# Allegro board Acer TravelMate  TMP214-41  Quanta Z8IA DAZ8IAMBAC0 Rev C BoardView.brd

Outline 238 x 219.5 mm; copper layers: TOP, SGND, IN1, SVCC, IN2, IN3, SGND1, IN4, SGND2, BOTTOM. Coordinates in mm from the lower left corner of the outline.

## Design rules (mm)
constraint set DEFAULT: min track width 0.114
net group W3.5-T1234B: nets VGA_VCCSENSE VGA_VSSSENSE
net group W4-T1234B: nets +1.2VSUS +VCC3V3A_SX_TCP0
net group W12-T1234B: nets +3VLCD_CON_R_C +VCONN_5V_3
net group W15-T134B: nets CLK_BIASREF DDR_RCOMP0
net group DFP-S4(3.5: nets PEX_TSTCLK PEX_TSTCLK# VMA_CLK0 VMA_CLK0# VMA_CLK1 VMA_CLK1# VMA_WCK01 VMA_WCK01# VMA_WCK23 VMA_WCK23# VMA_WCK45 VMA_WCK45# VMA_WCK67 VMA_WCK67#
net group DFP-S4.5(3.5: nets M_A_CLKN0 M_A_CLKN1 M_A_CLKP0 M_A_CLKP1 M_B_CLKN0 M_B_CLKN1 M_B_CLKP0 M_B_CLKP1
net group DFP-S4.5(3.5: nets CLK_PCIE_LANN CLK_PCIE_LANP CLK_PCIE_SSDN CLK_PCIE_SSDN_C CLK_PCIE_SSDP CLK_PCIE_SSDP_C CLK_PCIE_WLANN CLK_PCIE_WLANP CLK_VGA_N CLK_VGA_P CNV_WR_CLK_DN CNV_WR_CLK_DP CNV_WR_LANE0_DN CNV_WR_LANE0_DP CNV_WR_LANE1_DN CNV_WR_LANE1_DP CNV_WT_CLK_DN CNV_WT_CLK_DP CNV_WT_LANE0_DN CNV_WT_LANE0_DP CNV_WT_LANE1_DN CNV_WT_LANE1_DP DP_AUXN DP_AUXP DP_D0N DP_D0P DP_D1N DP_D1P GPU_CLK#_C GPU_CLK_C GPU_D0#_C GPU_D0_C GPU_D1#_C GPU_D1_C GPU_D2#_C GPU_D2_C HDMI_TXCN HDMI_TXCP HDMI_TXDN0 HDMI_TXDN1 HDMI_TXDN2 HDMI_TXDP0 HDMI_TXDP1 HDMI_TXDP2 INT_EDP_AUXN INT_EDP_AUXN_C INT_EDP_AUXP INT_EDP_AUXP_C INT_EDP_TXN0 INT_EDP_TXN0_C INT_EDP_TXN1 INT_EDP_TXN1_C INT_EDP_TXP0 INT_EDP_TXP0_C INT_EDP_TXP1 INT_EDP_TXP1_C PCIE4_RCOMPN PCIE4_RCOMPP PCIE_RCOMPN PCIE_RCOMPP PCIE_RXN3_WLAN PCIE_RXN5_SSD PCIE_RXN5_SSD_C PCIE_RXN6_SSD PCIE_RXN6_SSD_C PCIE_RXN7_SSD PCIE_RXN7_SSD_C PCIE_RXN8_SSD PCIE_RXN8_SSD_C PCIE_RXN9_LAN PCIE_RXN_LAN_L PCIE_RXP3_WLAN PCIE_RXP5_SSD PCIE_RXP5_SSD_C PCIE_RXP6_SSD PCIE_RXP6_SSD_C PCIE_RXP7_SSD PCIE_RXP7_SSD_C PCIE_RXP8_SSD PCIE_RXP8_SSD_C PCIE_RXP9_LAN PCIE_RXP_LAN_L PCIE_TXN3_WLAN PCIE_TXN3_WLAN_C PCIE_TXN5_SSD PCIE_TXN5_SSD_C PCIE_TXN6_SSD PCIE_TXN6_SSD_C PCIE_TXN7_SSD PCIE_TXN7_SSD_C PCIE_TXN8_SSD PCIE_TXN8_SSD_C PCIE_TXN9_LAN PCIE_TXN9_LAN_C PCIE_TXP3_WLAN PCIE_TXP3_WLAN_C PCIE_TXP5_SSD PCIE_TXP5_SSD_C PCIE_TXP6_SSD PCIE_TXP6_SSD_C PCIE_TXP7_SSD PCIE_TXP7_SSD_C PCIE_TXP8_SSD PCIE_TXP8_SSD_C PCIE_TXP9_LAN PCIE_TXP9_LAN_C PEG_RXN1 PEG_RXN1_C PEG_RXN2 PEG_RXN2_C PEG_RXN3 PEG_RXN3_C PEG_RXN4 PEG_RXN4_C PEG_RXP1 PEG_RXP1_C PEG_RXP2 PEG_RXP2_C PEG_RXP3 PEG_RXP3_C PEG_RXP4 PEG_RXP4_C PEG_TXN1 PEG_TXN1_C PEG_TXN2 PEG_TXN2_C PEG_TXN3 PEG_TXN3_C PEG_TXN4 PEG_TXN4_C PEG_TXP1 PEG_TXP1_C PEG_TXP2 PEG_TXP2_C PEG_TXP3 PEG_TXP3_C PEG_TXP4 PEG_TXP4_C SATA_RXN0_CN SATA_RXN0_HDD SATA_RXN0_IN SATA_RXN_OUT SATA_RXP0_CN SATA_RXP0_HDD SATA_RXP0_IN SATA_RXP_OUT SATA_TXN0_CN SATA_TXN0_HDD SATA_TXN0_IN SATA_TXN_OUT SATA_TXP0_CN SATA_TXP0_HDD SATA_TXP0_IN SATA_TXP_OUT TBT_LSX0_RXD TBT_LSX0_RXD_SOC TBT_LSX0_TXD TBT_LSX0_TXD_SOC TBTA_SBU1_CCG5_L TBTA_SBU1_CCG5_R TBTA_SBU1_CON_CCG5 TBTA_SBU2_CCG5_L TBTA_SBU2_CCG5_R TBTA_SBU2_CON_CCG5 TCP0_AUX_DN TCP0_AUX_DN_R TCP0_AUX_DP TCP0_AUX_DP_R TCP0_TX_N0 TCP0_TX_N0_C TCP0_TX_N1 TCP0_TX_N1_C TCP0_TX_P0 TCP0_TX_P0_C TCP0_TX_P1 TCP0_TX_P1_C TCP0_TXRX_N0 TCP0_TXRX_N0_C TCP0_TXRX_N1 TCP0_TXRX_N1_C TCP0_TXRX_P0 TCP0_TXRX_P0_C TCP0_TXRX_P1 TCP0_TXRX_P1_C TCRCOMP_DN TCRCOMP_DP USB30_RX1+ USB30_RX1+_C USB30_RX1- USB30_RX1-_C USB30_RX2+ USB30_RX2+_C USB30_RX2- USB30_RX2-_C USB30_RX4+ USB30_RX4- USB30_TX1+ USB30_TX1+_C USB30_TX1+_C_R USB30_TX1- USB30_TX1-_C USB30_TX1-_C_R USB30_TX2+ USB30_TX2+_C USB30_TX2+_C_R USB30_TX2- USB30_TX2-_C USB30_TX2-_C_R USB30_TX4+ USB30_TX4- USBP1+_CR USBP1-_CR USBP2+_TPC USBP2+_TPC_BOT USBP2+_TPC_TOP USBP2-_TPC USBP2-_TPC_BOT USBP2-_TPC_TOP USBP3+_LTE USBP3-_LTE USBP4+ USBP4+_R USBP4- USBP4-_R USBP5+_CAM USBP5+_CAM_C USBP5-_CAM USBP5-_CAM_C USBP6+_HUB USBP6+_HUB_R USBP6+_HUB_SM USBP6+_HUB_SM_R USBP6+_HUB_TS USBP6+_HUB_TS_R USBP6-_HUB USBP6-_HUB_R USBP6-_HUB_SM USBP6-_HUB_SM_R USBP6-_HUB_TS USBP6-_HUB_TS_R USBP7+_FP_P2 USBP7+_FP_P4 USBP7-_FP_P2 USBP7-_FP_P4 USBP8+ USBP8+_C USBP8+_C_R USBP8- USBP8-_C USBP8-_C_R USBP9+_DB USBP9+_DB_RS232 USBP9+_DB_USB USBP9-_DB USBP9-_DB_RS232 USBP9-_DB_USB USBP10+_BT USBP10-_BT VGA_DDI2_AUXN_C VGA_DDI2_AUXP_C VGA_DDI2_TXN0_C VGA_DDI2_TXN1_C VGA_DDI2_TXP0_C VGA_DDI2_TXP1_C
net group DFP-S4.5W4.5-TB: nets TBTA_RX1_N TBTA_RX1_P TBTA_RX2_N TBTA_RX2_P TBTA_SSRX1_N TBTA_SSRX1_N_C TBTA_SSRX1_P TBTA_SSRX1_P_C TBTA_SSRX2_N TBTA_SSRX2_N_C TBTA_SSRX2_P TBTA_SSRX2_P_C TBTA_SSTX1_N TBTA_SSTX1_N_C TBTA_SSTX1_P TBTA_SSTX1_P_C TBTA_SSTX2_N TBTA_SSTX2_N_C TBTA_SSTX2_P TBTA_SSTX2_P_C TBTA_TX1_N TBTA_TX1_P TBTA_TX2_N TBTA_TX2_P
net group DFP-S5(4.5: nets M_A_DQSN0 M_A_DQSN1 M_A_DQSN2 M_A_DQSN3 M_A_DQSN4 M_A_DQSN5 M_A_DQSN6 M_A_DQSN7 M_A_DQSP0 M_A_DQSP1 M_A_DQSP2 M_A_DQSP3 M_A_DQSP4 M_A_DQSP5 M_A_DQSP6 M_A_DQSP7 M_B_DQSN0 M_B_DQSN1 M_B_DQSN2 M_B_DQSN3 M_B_DQSN4 M_B_DQSN5 M_B_DQSN6 M_B_DQSN7 M_B_DQSP0 M_B_DQSP1 M_B_DQSP2 M_B_DQSP3 M_B_DQSP4 M_B_DQSP5 M_B_DQSP6 M_B_DQSP7
net group DFP-S5.5(7)W3.5(3.2: nets MDI0+ MDI0+_1 MDI0- MDI0-_1 MDI1+ MDI1+_1 MDI1- MDI1-_1 MDI2+ MDI2+_1 MDI2- MDI2-_1 MDI3+ MDI3+_1 MDI3- MDI3-_1
net group DFP-S5.5(7: nets C_IN_CLK C_IN_CLK# C_TX0_HDMI+ C_TX0_HDMI- C_TX1_HDMI+ C_TX1_HDMI- C_TX2_HDMI+ C_TX2_HDMI- TX0_HDMI+ TX0_HDMI- TX1_HDMI+ TX1_HDMI- TX2_HDMI+ TX2_HDMI- TXC_HDMI+ TXC_HDMI-
net group GND: nets GND
net group W4.5(3.5: nets DDR4_DRAMRST# DRAM_RESET# M_A_DQ0 M_A_DQ1 M_A_DQ2 M_A_DQ3 M_A_DQ4 M_A_DQ5 M_A_DQ6 M_A_DQ7 M_A_DQ8 M_A_DQ9 M_A_DQ10 M_A_DQ11 M_A_DQ12 M_A_DQ13 M_A_DQ14 M_A_DQ15 M_A_DQ16 M_A_DQ17 M_A_DQ18 M_A_DQ19 M_A_DQ20 M_A_DQ21 M_A_DQ22 M_A_DQ23 M_A_DQ24 M_A_DQ25 M_A_DQ26 M_A_DQ27 M_A_DQ28 M_A_DQ29 M_A_DQ30 M_A_DQ31 M_A_DQ32 M_A_DQ33 M_A_DQ34 M_A_DQ35 M_A_DQ36 M_A_DQ37 M_A_DQ38 M_A_DQ39 M_A_DQ40 M_A_DQ41 M_A_DQ42 M_A_DQ43 M_A_DQ44 M_A_DQ45 M_A_DQ46 M_A_DQ47 M_A_DQ48 M_A_DQ49 M_A_DQ50 M_A_DQ51 M_A_DQ52 M_A_DQ53 M_A_DQ54 M_A_DQ55 M_A_DQ56 M_A_DQ57 M_A_DQ58 M_A_DQ59 M_A_DQ60 M_A_DQ61 M_A_DQ62 M_A_DQ63 M_B_DQ0 M_B_DQ1 M_B_DQ2 M_B_DQ3 M_B_DQ4 M_B_DQ5 M_B_DQ6 M_B_DQ7 M_B_DQ8 M_B_DQ9 M_B_DQ10 M_B_DQ11 M_B_DQ12 M_B_DQ13 M_B_DQ14 M_B_DQ15 M_B_DQ16 M_B_DQ17 M_B_DQ18 M_B_DQ19 M_B_DQ20 M_B_DQ21 M_B_DQ22 M_B_DQ23 M_B_DQ24 M_B_DQ25 M_B_DQ26 M_B_DQ27 M_B_DQ28 M_B_DQ29 M_B_DQ30 M_B_DQ31 M_B_DQ32 M_B_DQ33 M_B_DQ34 M_B_DQ35 M_B_DQ36 M_B_DQ37 M_B_DQ38 M_B_DQ39 M_B_DQ40 M_B_DQ41 M_B_DQ42 M_B_DQ43 M_B_DQ44 M_B_DQ45 M_B_DQ46 M_B_DQ47 M_B_DQ48 M_B_DQ49 M_B_DQ50 M_B_DQ51 M_B_DQ52 M_B_DQ53 M_B_DQ54 M_B_DQ55 M_B_DQ56 M_B_DQ57 M_B_DQ58 M_B_DQ59 M_B_DQ60 M_B_DQ61 M_B_DQ62 M_B_DQ63
net group W4.5(3.5: nets ACZ_BCLK ACZ_RST# ACZ_SDOUT ACZ_SYNC BIOS_WP# CPU_SVID_CLK CPU_SVID_DAT CPU_VIDALERT# DMIC_CLK DMIC_CLK_L DMIC_CLK_L_C DMIC_CLK_PCH DMIC_DAT DMIC_DAT_L DMIC_DAT_L_C DMIC_DAT_PCH ESPI_0 ESPI_0_R ESPI_1 ESPI_1_R ESPI_2 ESPI_2_R ESPI_3 ESPI_3_R ESPI_CLK ESPI_CLK_R ESPI_CS# ESPI_CS#_R ESPI_RESET# ESPI_RESET#_EC ESPI_RESET#_R H_PROCHOT# HOLD# N17011437 PCH_AZ_CODEC_BITCLK PCH_AZ_CODEC_RST# PCH_AZ_CODEC_SDIN0 PCH_AZ_CODEC_SDOUT PCH_AZ_CODEC_SYNC PCH_JTAGX PCH_SPI0_CLK PCH_SPI0_CLK_R PCH_SPI0_CS0# PCH_SPI0_CS0#_R PCH_SPI0_IO2 PCH_SPI0_IO2_R PCH_SPI0_IO3 PCH_SPI0_IO3_R PCH_SPI0_SI PCH_SPI0_SI_R PCH_SPI0_SO PCH_SPI0_SO_R PCH_SPI1_CLK_R PCH_SPI1_SI_R PCH_SPI1_SO_R PCH_SPI_CS0#_R PCH_TCK PCH_TDI PCH_TDO PCH_TMS PCH_TRST# PEGX_RST# PEGX_RST#_C PLTRST# PLTRST#_LAN PM_THRMTRIP# PROCHOT#_CPU PROCHOT_EC PROCPWRGD SD_CDZ SD_CDZ_R SD_CLK SD_CLK_R SD_CMD SD_CMD_R SD_D0/MS_D6 SD_D0/MS_D6_R SD_D1/MS_D7 SD_D1/MS_D7_R SD_D2/MS_D5 SD_D2/MS_D5_R SD_D3/MS_D4 SD_D3/MS_D4_R SD_WP/MS_D1 SPI0_CLK_R SPI0_CS0#_R SPI0_SI_R SPI0_SO_R SPI_TPM_CS# SPI_TPM_CS#_TPM TBTA_SBU1_TX_BB TBTA_SBU2_RX_BB TCP0_FLASH_CLK TCP0_FLASH_CS# TCP0_FLASH_DI TCP0_FLASH_DO TCP0_FLASH_HOLD# TCP0_FLASH_WP# TPM_SPI0_CLK TPM_SPI0_SI TPM_SPI0_SO USB_OC2# VGA_DDC_CLK_RT VGA_DDC_DAT_RT VR_SVID_ALERT# VR_SVID_CLK VR_SVID_DATA XDP_TCK XDP_TDI_CPU XDP_TDO_CPU XDP_TMS_CPU XDP_TRST#
net group W4.5(3.5: nets 2ND_MBCLK 2ND_MBDATA 27M_XTAL_IN 27M_XTAL_OUT A_SCL A_SDA BRIGHT CL_CLK CL_DATA CL_RST# CNV_BRI_DT CNV_BRI_DT_R CNV_BRI_RSP CNV_BRI_RSP_L CNV_MFUART2_RXD CNV_MFUART2_TXD CNV_RF_RESET# CNV_RF_RESET#_L CNV_RGI_DT CNV_RGI_DT_R CNV_RGI_RSP CNV_RGI_RSP_L DDPC_CLK DDPC_DATA DISP_ON DP_HPD EC_CCG_I2C_SCL EC_CCG_I2C_SCL_D EC_CCG_I2C_SDA EC_CCG_I2C_SDA_D EC_PECI EC_PECR_R GPUT_CLK_L GPUT_DATA_L HDMI_DDCCLK HDMI_DDCCLK_DDP3 HDMI_DDCDATA HDMI_HPD HDMI_HPD_C HDMI_HPD_DC HDMI_HPD_PCH HDMI_SCLK HDMI_SDATA I2C1_CLK_TP I2C1_DATA_TP I2C2_SCL_SEN_HUB I2C2_SDA_SEN_HUB I2C3_SCL_NFC I2C3_SDA_NFC I219_PCH_SMCLK I219_PCH_SMDATA I219_SMCLK I219_SMDATA ISH_I2C1_SCL ISH_I2C1_SDA LAN_XTAL1 MBCLK MBCLK_THM MBDATA MBDATA_THM N24720119 N24720120 N27826847 N27826858 N27826869 N36446693 N64506943 NFC_I2C_SCL NFC_I2C_SDA PCH_BLON_C PCH_DISP_ON PCH_DPST_PWM PCH_LVDS_BLON PCH_SMBCLK PCH_SMBDATA PCIE_CLKREQ_LAN# PCIE_CLKREQ_SSD# PCIE_CLKREQ_VGA# PCIE_CLKREQ_WLAN# PULSAR_38P4M_REFCLK PWM-VID RT_I2C_SCL RT_I2C_SDA RTC_RST# RTC_X1 RTC_X1_R RTC_X2 RTC_X2_R SCARDCLK SCARDDATA SCL_GSENSOR SCL_GSENSOR_MB SCL_HUB_TO_CPU SDA_GSENSOR SDA_GSENSOR_MB SDA_HUB_TO_CPU SMB_ME1_CLK SMB_ME1_CLK_D SMB_ME1_DAT SMB_ME1_DAT_D SMB_RUN_CLK SMB_RUN_DAT SMB_SML0_CLK SMB_SML0_DAT SRTC_RST# SUSCLK_32K SUSCLK_32KHZ SYS_SHDN# TBT_LSX2_RXD TP_SMB_CLK TP_SMB_DATA ULT_EDP_HPD ULT_EDP_HPD_R VCC_AUX_SENSE VCCSENSE VGA_SDA VGA_SLK VSS_AUX_SENSE VSSSENSE XIN XOUT XTAL1 XTAL2 XTAL_38P4M_IN XTAL_38P4M_IN_R XTAL_38P4M_OUT XTAL_38P4M_OUT_R XTAL_TCP0_25MHZ_IN XTAL_TCP0_25MHZ_OUT
net group W4.5-T1234B: nets +VIN
net group W4.5-TB: nets CRT_B CRT_B1 CRT_G CRT_G1 CRT_R CRT_R1 CRTHSYNC CRTHSYNC_R CRTVSYNC CRTVSYNC_R
net group W6(4: nets M_A_A0 M_A_A1 M_A_A2 M_A_A3 M_A_A4 M_A_A5 M_A_A6 M_A_A7 M_A_A8 M_A_A9 M_A_A10 M_A_A11 M_A_A12 M_A_A13 M_A_ACT# M_A_ALERT# M_A_BG#0 M_A_BG#1 M_A_BS#0 M_A_BS#1 M_A_CAS# M_A_CKE0 M_A_CKE1 M_A_CS#0 M_A_CS#1 M_A_DIM0_ODT0 M_A_DIM0_ODT1 M_A_PARITY M_A_RAS# M_A_WE# M_B_A0 M_B_A1 M_B_A2 M_B_A3 M_B_A4 M_B_A5 M_B_A6 M_B_A7 M_B_A8 M_B_A9 M_B_A10 M_B_A11 M_B_A12 M_B_A13 M_B_ACT# M_B_ALERT# M_B_BG#0 M_B_BG#1 M_B_BS#0 M_B_BS#1 M_B_CAS# M_B_CKE0 M_B_CKE1 M_B_CS#0 M_B_CS#1 M_B_DIM0_ODT0 M_B_DIM0_ODT1 M_B_PARITY M_B_RAS# M_B_WE#
net group W6-T1234B: nets +3VPCU_EC
net group W7(5: nets FBA_CMD0 FBA_CMD1 FBA_CMD2 FBA_CMD3 FBA_CMD4 FBA_CMD5 FBA_CMD6 FBA_CMD7 FBA_CMD8 FBA_CMD9 FBA_CMD10 FBA_CMD11 FBA_CMD12 FBA_CMD13 FBA_CMD14 FBA_CMD15 FBA_CMD16 FBA_CMD17 FBA_CMD18 FBA_CMD19 FBA_CMD20 FBA_CMD21 FBA_CMD22 FBA_CMD23 FBA_CMD24 FBA_CMD25 FBA_CMD26 FBA_CMD27 FBA_CMD28 FBA_CMD29 FBA_CMD30 FBA_CMD31 FBA_DBI0 FBA_DBI1 FBA_DBI2 FBA_DBI3 FBA_DBI4 FBA_DBI5 FBA_DBI6 FBA_DBI7 FBA_EDC0 FBA_EDC1 FBA_EDC2 FBA_EDC3 FBA_EDC4 FBA_EDC5 FBA_EDC6 FBA_EDC7 VMA_DQ0 VMA_DQ1 VMA_DQ2 VMA_DQ3 VMA_DQ4 VMA_DQ5 VMA_DQ6 VMA_DQ7 VMA_DQ8 VMA_DQ9 VMA_DQ10 VMA_DQ11 VMA_DQ12 VMA_DQ13 VMA_DQ14 VMA_DQ15 VMA_DQ16 VMA_DQ17 VMA_DQ18 VMA_DQ19 VMA_DQ20 VMA_DQ21 VMA_DQ22 VMA_DQ23 VMA_DQ24 VMA_DQ25 VMA_DQ26 VMA_DQ27 VMA_DQ28 VMA_DQ29 VMA_DQ30 VMA_DQ31 VMA_DQ32 VMA_DQ33 VMA_DQ34 VMA_DQ35 VMA_DQ36 VMA_DQ37 VMA_DQ38 VMA_DQ39 VMA_DQ40 VMA_DQ41 VMA_DQ42 VMA_DQ43 VMA_DQ44 VMA_DQ45 VMA_DQ46 VMA_DQ47 VMA_DQ48 VMA_DQ49 VMA_DQ50 VMA_DQ51 VMA_DQ52 VMA_DQ53 VMA_DQ54 VMA_DQ55 VMA_DQ56 VMA_DQ57 VMA_DQ58 VMA_DQ59 VMA_DQ60 VMA_DQ61 VMA_DQ62 VMA_DQ63
net group W7-T1234B: nets +1.2V_HDMI
net group W8-T134B: nets CPU_POPI_RCOMP TBT1_CC1 TBT1_CC2
net group W8-T1234B: nets +1.05V_LAN +1.8V_DEEP_SUS +1V8_AON +3V +3V3_TPM +3V_DEEP_SUS +3V_LAN +3V_LDO_EC +3V_RTC +3V_S5 +3V_WLAN_P +5V_PVDD +5VA +5VPCU +A3VPCU +AZA_VDD +SENSOR_POWER +USBPWR0 +VCC0V9_SVR_TCP0 +VCC0V9_SVR_TCP0_PHASE +VCC1.05_OUT_FET +VCCPRIM_3P3 +VCCRTC +VCCST AVDD2 DVDD_IO RSET
net group W10-T134B: nets +SMDDR_VREF_DQ1_M1 CFG_RCOMP CNV_WT_RCOMP CSI_RCOMP DP_RCOMP GPP_RCOMP PCH_OPI_RCOMP SNDW_RCOMP USB2_COMP
net group W10-T1234B: nets +1.8V_S5 +1V8_GFX_MAIN +3V_EC +3VPCU_ECPLL +VDDQ_VTT +VGPU_CORE DCPRTC NV_PLLVDD SP_PLLVDD TYPEC1_USB0
net group W13-T1234B: nets +1.35V_GFX
net group W14-T1234B: nets +2.5V_SUS
net group W15-T1234B: nets +1.03_GFX +3V_SSD +V3.3DX_RT_TCP0 +VCCSTG_S2 FB_CAL_PD_VDDQ HP-L2 HP-L3 HP-R2 HP-R3 HP_JD# LINE1-L LINE1-R LINE1-VREFO-L LINE1-VREFO-R MIC2-VREFO SENSEA
net group W20-T134B: nets +SMDDR_VREF_DIMM FBA_VREFC_1 FBA_VREFC_2 SM_VREF SMDDR_VREF_DQ1_M3
net group W20-T1234B: nets +1.05V_EXT +3V_RTC_0 +3V_RTC_1 +3V_RTC_2 +3VLCD_CON +3VLCD_CON_R +5V_HDMIC +5V_KB +601_VCC +CRT_VDDA33 +USBPWR1 +USBPWRD2 +VCCSTG +VDDQ +VIN_BLIGHT +VNN_EXT CRT_VCC_R FB_CAL_TERM_GND
net group W40-T1234B: nets L_SPK+ L_SPK+_1 L_SPK+_1_VIKI L_SPK- L_SPK-_1 L_SPK-_1_VIKI R_SPK+ R_SPK+_1 R_SPK+_1_VIKI R_SPK- R_SPK-_1 R_SPK-_1_VIKI RING2 SLEEVE
net group W60-T1234B: nets +1.05V_LAN_REGOUT

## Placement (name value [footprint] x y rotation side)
C202  0.1u/6.3V_2  [C0201]  181.78 114.58 180 bottom
C203  0.1u/6.3V_2  [C0201]  181.78 113.81 180 bottom
C212  *0.1u/6.3V_2  [C0201]  79.93 96.29 0 top
C249  *0.1u/6.3V_2  [C0201]  45.74 145.21 270 top
C250  1u/10V_2  [C0201]  52.37 135.53 270 top
C251  1u/10V_2  [C0201]  46.65 103.7 270 top
C252  1u/10V_2  [C0201]  44.5 138.96 270 top
C253  1u/10V_2  [C0201]  48.8 105.79 90 top
C254  1u/10V_2  [C0201]  46.65 130.83 0 top
C255  *1u/10V_2  [C0201]  47.54 103.7 270 top
C256  1u/10V_2  [C0201]  55.42 124.74 180 top
C257  *1u/10V_2  [C0201]  47.78 105.79 90 top
C258  *1u/10V_2  [C0201]  53.13 135.53 270 top
C259  10u/6.3V_4  [C0402]  45.77 103.78 90 top
C260  *1u/10V_2  [C0201]  55.16 110.64 0 top
C261  *10u/6.3V_4  [C0402]  56.47 107.2 270 top
C262  *1u/10V_2  [C0201]  47.29 168.81 90 top
C263  *1u/10V_2  [C0201]  44.34 144.8 90 top
C264  0.1u/6.3V_2  [C0201]  46.48 128.56 0 top
C265  2.2u/10V_4  [C0402]  46.02 127.04 180 top
C266  0.022u/25V_4  [C0402]  45.38 119.66 90 top
C267  10u/6.3V_4  [C0402]  47.46 115.51 0 top
C268  10u/6.3V_4  [C0402]  44.45 133.83 270 top
C269  1u/10V_2  [C0201]  51.61 103.07 270 top
C270  10u/6.3V_4  [C0402]  44.5 140.74 90 top
C271  *1u/10V_2  [C0201]  50.72 103.07 270 top
C272  10u/6.3V_4  [C0402]  58.58 141.84 180 top
C273  *10u/6.3V_4  [C0402]  51.27 106.69 270 top
C274  *10u/6.3V_4  [C0402]  46.64 158.99 180 top
C275  10u/6.3V_4  [C0402]  50.26 106.69 270 top
C276  *10u/6.3V_4  [C0402]  54.53 133.75 0 top
C277  *10u/6.3V_4  [C0402]  54.02 144.55 270 top
C278  0.1u/6.3V_2  [C0201]  53.69 106.4 0 top
C279  *10u/6.3V_4  [C0402]  44.5 143.02 270 top
C280  2.2u/10V_4  [C0402]  52.68 106.84 270 top
C347  EV@22u/6.3V_6  [C0603]  141.19 209.9 180 bottom
C348  EV@10u/6.3V_4  [C0402]  142.82 208.33 270 bottom
C349  EV@4.7u/6.3V_4  [C0402]  143.66 209.8 0 bottom
C350  EV@4.7u/6.3V_4  [C0402]  141.73 211.2 180 bottom
C351  EV@1u/10V_2  [C0201]  130.02 195.09 90 top
C352  EV@1u/10V_2  [C0201]  134.16 195.73 270 top
C353  EV@1u/10V_2  [C0201]  135.43 191.54 270 top
C354  EV@1u/10V_2  [C0201]  143.05 209.19 270 top
C355  EV@47u/6.3V_6  [C0603]  138.45 210.86 270 bottom
C356  EV@4.7u/6.3V_4  [C0402]  140.81 208.21 0 bottom
C357  EV@4.7u/6.3V_4  [C0402]  134.15 193.54 90 top
C358  EV@0.22u/6.3V_2  [C0201]  116.63 201.32 90 top
C359  EV@22u/6.3V_6  [C0603]  131.62 210.33 180 bottom
C360  EV@4.7u/6.3V_4  [C0402]  146.65 206.12 0 bottom
C362  EV@1u/10V_2  [C0201]  135 198.4 270 top
C363  EV@10u/6.3V_4  [C0402]  143.66 210.79 0 bottom
C364  *EV@0.1u/6.3V_2  [C0201]  118.79 208.05 90 bottom
C365  EV@1u/10V_2  [C0201]  130.04 191.21 90 top
C366  EV@4.7u/6.3V_4  [C0402]  136.54 198.24 180 top
C367  EV@4.7u/6.3V_4  [C0402]  134.15 191.77 270 top
C368  EV@4.7u/6.3V_4  [C0402]  126.64 194.56 270 top
C369  EV@4.7u/6.3V_4  [C0402]  131.59 190.24 0 top
C370  EV@0.22u/6.3V_2  [C0201]  115.87 201.32 90 top
C371  EV@0.1u/6.3V_2  [C0201]  126.54 185.95 270 top
C372  EV@4.7u/6.3V_4  [C0402]  133.37 190.24 180 top
C373  EV@4.7u/6.3V_4  [C0402]  127.83 191.77 270 top
C374  EV@4.7u/6.3V_4  [C0402]  132.99 195.37 270 top
C375  EV@0.1u/6.3V_2  [C0201]  128.77 187.96 270 top
C376  EV@4.7u/6.3V_4  [C0402]  126.61 188.03 270 top
C377  EV@22u/6.3V_6  [C0603]  144.29 208 90 bottom
C378  EV@1u/10V_2  [C0201]  127.47 188.03 90 top
C379  EV@4.7u/6.3V_4  [C0402]  146.65 204.85 0 bottom
C380  EV@4.7u/6.3V_4  [C0402]  131.59 188.84 0 top
C381  EV@10u/6.3V_4  [C0402]  146.47 207.62 90 bottom
C382  EV@0.22u/6.3V_2  [C0201]  128.7 208.3 270 top
C383  EV@10u/6.3V_4  [C0402]  145.51 207.64 90 bottom
C384  EV@0.22u/6.3V_2  [C0201]  127.93 208.3 270 top
C385  EV@330u/2V_7343H2.22  [CC7343]  134.54 215.03 180 bottom
C386  EV@22u/6.3V_6  [C0603]  129.96 188.23 90 top
C387  EV@47u/6.3V_6  [C0603]  131.62 211.86 180 bottom
C388  EV@10u/6.3V_4  [C0402]  134.79 207.67 180 bottom
C389  *EV@10u/6.3V_4  [C0402]  138.9 207.66 180 bottom
C391  *EV@10u/6.3V_4  [C0402]  136.57 207.67 0 bottom
C392  EV@4.7u/6.3V_4  [C0402]  163.41 207.98 180 top
C393  *EV@10u/6.3V_4  [C0402]  132.41 207.67 0 bottom
C394  EV@1u/10V_2  [C0201]  115.4 190.88 270 top
C395  EV@1u/10V_2  [C0201]  127.93 198.14 270 top
C396  EV@4.7u/6.3V_4  [C0402]  132.41 208.81 0 bottom
C397  EV@4.7u/6.3V_4  [C0402]  138.9 208.81 180 bottom
C398  EV@0.1u/6.3V_2  [C0201]  125.52 189 90 top
C399  EV@1u/10V_2  [C0201]  144.32 208.3 90 top
C400  EV@4.7u/6.3V_4  [C0402]  136.57 208.81 0 bottom
C401  EV@0.1u/6.3V_2  [C0201]  114.41 190.88 270 top
C402  EV@1u/10V_2  [C0201]  128.77 198.14 270 top
C403  EV@4.7u/6.3V_4  [C0402]  134.79 208.81 180 bottom
C406  EV@4.7u/6.3V_4  [C0402]  127.83 189.99 90 top
C407  EV@4.7u/6.3V_4  [C0402]  129.56 190.17 180 top
C408  EV@4.7u/6.3V_4  [C0402]  127.89 195.67 270 top
C409  EV@4.7u/6.3V_4  [C0402]  127.83 193.54 90 top
C410  EV@1u/10V_2  [C0201]  133.65 197.25 90 top
C411  EV@1u/10V_2  [C0201]  131.16 193.7 270 top
C412  EV@10u/6.3V_4  [C0402]  132.96 191.77 270 top
C413  EV@47u/6.3V_6  [C0603]  109.01 213.38 315 bottom
C414  *EV@47u/6.3V_6  [C0603]  132.16 209.85 270 top
C415  EV@10u/6.3V_4  [C0402]  126.81 196.61 270 top
C416  EV@47u/6.3V_6  [C0603]  106.78 203.01 90 top
C417  *EV@47u/6.3V_6  [C0603]  137.03 210.87 90 bottom
C418  EV@10u/6.3V_4  [C0402]  132.96 193.54 90 top
C419  EV@47u/6.3V_6  [C0603]  130.57 198.6 0 top
C420  *EV@47u/6.3V_6  [C0603]  114.12 207.24 180 bottom
C421  EV@10u/6.3V_4  [C0402]  131.16 191.77 270 top
C422  EV@47u/6.3V_6  [C0603]  113.59 199.84 0 top
C423  *EV@47u/6.3V_6  [C0603]  134.83 209.88 90 top
C424  EV@10u/6.3V_4  [C0402]  131.16 195.32 270 top
C425  EV@0.1u/6.3V_2  [C0201]  125.85 197.39 90 top
C426  EV@47u/6.3V_6  [C0603]  136.49 209.85 90 top
C427  *EV@47u/6.3V_6  [C0603]  110.03 214.4 135 bottom
C428  EV@10u/6.3V_4  [C0402]  131.59 197.35 0 top
C429  EV@4.7u/6.3V_4  [C0402]  125.04 199.24 180 top
C430  EV@10u/6.3V_4  [C0402]  130.07 193.54 90 top
C431  EV@4.7u/6.3V_4  [C0402]  124.77 197.31 270 top
C432  EV@10u/6.3V_4  [C0402]  125.37 195.32 90 top
C433  EV@0.1u/6.3V_2  [C0201]  110.21 184.27 180 bottom
C438  EV@1u/10V_2  [C0201]  147.82 182.97 270 top
C439  EV@1u/10V_2  [C0201]  136.29 194.2 0 top
C440  EV@1u/10V_2  [C0201]  149.17 182.98 270 top
C441  EV@1u/10V_2  [C0201]  165.4 194.84 90 top
C442  EV@1u/10V_2  [C0201]  162.4 194.71 90 top
C443  EV@10u/6.3V_4  [C0402]  135.4 189.86 180 top
C444  EV@10u/6.3V_4  [C0402]  136.3 193.23 180 top
C445  *EV@22u/6.3V_6  [C0603]  135.93 196.36 180 top
C446  *EV@22u/6.3V_6  [C0603]  147.08 192.15 90 bottom
C447  EV@1u/10V_2  [C0201]  135.43 188.87 0 top
C448  EV@10u/6.3V_4  [C0402]  136.29 195.17 180 top
C449  EV@1u/10V_2  [C0201]  134.41 187.98 270 top
C450  EV@1u/10V_2  [C0201]  133.14 188.36 270 top
C451  EV@22u/6.3V_6  [C0603]  145.43 192.15 90 bottom
C452  EV@0.1u/6.3V_2  [C0201]  129.84 208.94 90 bottom
C453  EV@22u/6.3V_4  [C0402]  136.16 187.7 180 top
C454  EV@0.1u/6.3V_2  [C0201]  137.21 192.17 180 top
C455  EV@0.1u/6.3V_2  [C0201]  132.38 186.71 0 top
C456  EV@0.1u/6.3V_2  [C0201]  115.09 193.79 0 top
C457  EV@0.1u/6.3V_2  [C0201]  115.42 195.91 270 top
C458  *EV@22u/6.3V_4  [C0402]  125.1 190.31 0 top
C459  EV@0.1u/6.3V_2  [C0201]  126.09 192.75 180 top
C460  EV@0.1u/6.3V_2  [C0201]  126.09 191.79 180 top
C461  *EV@10u/6.3V_4  [C0402]  115.42 197.64 90 top
C462  *EV@47u/6.3V_6  [C0603]  112.95 197.78 90 top
C463  EV@12p/50V_4  [C0402]  127.91 178.3 180 bottom
C464  EV@12p/50V_4  [C0402]  126.13 178.3 0 bottom
C471  EV@22u/6.3V_6  [C0603]  167.01 192.26 180 top
C472  EV@22u/6.3V_6  [C0603]  162.7 185.16 0 top
C473  EV@22u/6.3V_6  [C0603]  163.19 168.04 90 bottom
C474  EV@22u/6.3V_6  [C0603]  148.99 207.23 0 bottom
C475  EV@22u/6.3V_6  [C0603]  152.8 193.92 0 top
C476  EV@22u/6.3V_6  [C0603]  146.39 185.39 90 bottom
C477  EV@1u/10V_2  [C0201]  154.48 195.48 0 top
C478  EV@1u/10V_2  [C0201]  165.15 176.3 180 top
C479  EV@1u/10V_2  [C0201]  158.03 179.98 90 top
C480  EV@1u/10V_2  [C0201]  158.01 202.36 90 top
C481  EV@1u/10V_2  [C0201]  159.94 205.89 0 top
C482  EV@1u/10V_2  [C0201]  160.83 198.65 270 top
C483  EV@1u/10V_2  [C0201]  153.59 175.92 90 top
C484  EV@10u/6.3V_4  [C0402]  165.37 198.5 270 top
C485  *EV@22u/6.3V_6  [C0603]  164.92 200.71 180 top
C486  *EV@22u/6.3V_6  [C0603]  148.99 205.74 0 bottom
C487  EV@22u/6.3V_6  [C0603]  158.95 209.95 270 bottom
C488  EV@22u/6.3V_6  [C0603]  162.7 187.07 0 top
C489  EV@22u/6.3V_6  [C0603]  148.99 204.21 0 bottom
C490  EV@22u/6.3V_6  [C0603]  147.93 185.48 90 bottom
C491  EV@1u/10V_2  [C0201]  165.87 182.96 180 top
C492  EV@1u/10V_2  [C0201]  156.64 205.89 0 top
C493  EV@1u/10V_2  [C0201]  158.54 205 180 top
C494  EV@1u/10V_2  [C0201]  156.76 181.38 90 top
C495  EV@1u/10V_2  [C0201]  156.64 198.14 180 top
C496  EV@1u/10V_2  [C0201]  156.76 176.17 270 top
C497  EV@1u/10V_2  [C0201]  157.91 169.44 180 bottom
C498  EV@1u/10V_2  [C0201]  164.38 202.08 270 top
C499  EV@1u/10V_2  [C0201]  155.87 169.44 0 bottom
C500  EV@10u/6.3V_4  [C0402]  163.34 206.68 180 top
C501  EV@10u/6.3V_4  [C0402]  162.45 179.7 0 top
C502  EV@10u/6.3V_4  [C0402]  154.6 178.99 180 top
C503  *EV@22u/6.3V_6  [C0603]  149.46 185.48 90 bottom
C504  *EV@22u/6.3V_6  [C0603]  160.04 169.16 180 bottom
C505  EV@820p/50V_4  [C0402]  159.91 187.45 180 top
C506  EV@820p/50V_4  [C0402]  158.64 192.5 0 top
C508  1u/25V_4  [C0402]  22.65 100.35 270 top
C509  100u/6.3V_12  [C1206]  19.48 96.54 180 bottom
C510  470p/50V_4  [C0402]  23.79 94.31 0 top
C511  0.1u/6.3V_2  [C0201]  23.79 96.42 180 top
C512  1u/10V_2  [C0201]  22.65 92.22 270 bottom
C513  *1.6p/50V_4  [C0402]  21.86 89.43 270 top
C515  470p/50V_4  [C0402]  20.11 88.92 270 bottom
C516  0.1u/6.3V_2  [C0201]  18.84 88.64 90 bottom
C517  100u/6.3V_12  [C1206]  19.83 90.9 0 bottom
C518  *1.6p/50V_4  [C0402]  21.86 91.21 90 top
C519  0.1u/6.3V_2  [C0201]  24.05 88.03 90 top
C520  0.1u/6.3V_2  [C0201]  24.81 88.03 90 top
C521  *1.6p/50V_4  [C0402]  20.51 91.79 0 top
C522  *1.6p/50V_4  [C0402]  20.51 92.96 0 top
C523  *1.6p/50V_4  [C0402]  24.71 105.2 0 top
C524  1u/10V_2  [C0201]  220.83 110.44 0 bottom
C526  *1.6p/50V_4  [C0402]  24.71 106.4 0 top
C527  470p/50V_4  [C0402]  218.18 104.67 180 bottom
C528  0.1u/6.3V_2  [C0201]  221.03 104.67 180 bottom
C529  *100u/6.3V_12  [C1206]  220.77 107.59 90 bottom
C530  0.1u/6.3V_2  [C0201]  25.83 107.59 180 top
C531  0.1u/6.3V_2  [C0201]  25.83 108.35 180 top
C532  *1.6p/50V_4  [C0402]  22.32 107.36 0 top
C533  *1.6p/50V_4  [C0402]  22.32 108.56 0 top
C536  0.1u/25V_2  [C0201]  75.38 190.32 180 bottom
C537  0.01u/50V_4  [C0402]  75.36 191.16 0 bottom
C542  4.7u/25V_6  [C0603]  77.9 189.15 0 bottom
C543  0.1u/6.3V_2  [C0201]  72.97 192.81 0 top
C544  100p/50V_2  [C0201]  74.29 190.84 270 top
C545  *22u/6.3V_6  [C0603]  73.22 190.67 270 top
C546  0.1u/6.3V_2  [C0201]  71.19 189.63 90 bottom
C547  10p/25V_2  [C0201]  54.27 190.9 270 bottom
C548  10p/25V_2  [C0201]  54.27 191.92 90 bottom
C550  0.1u/6.3V_2  [C0201]  74.47 189.51 0 top
C551  CRT@4.7u/6.3V_4  [C0402]  25.95 157.63 0 top
C552  0.1u/6.3V_2  [C0201]  66.21 190.78 270 bottom
C553  0.1u/6.3V_2  [C0201]  65.45 190.78 270 bottom
C554  0.1u/6.3V_2  [C0201]  64.56 190.78 270 bottom
C555  0.1u/6.3V_2  [C0201]  63.8 190.78 270 bottom
C556  0.1u/6.3V_2  [C0201]  67.36 190.78 270 bottom
C557  0.1u/6.3V_2  [C0201]  68.12 190.78 270 bottom
C558  33p/25V_2  [C0201]  68.37 188.49 90 bottom
C559  1u/10V_2  [C0201]  71.55 193.95 0 top
C560  0.01u/50V_4  [C0402]  78.28 192.68 180 top
C561  0.1u/6.3V_2  [C0201]  78.3 190.65 0 top
C562  10u/6.3V_4  [C0402]  78.28 191.67 180 top
C563  2.2u/10V_4  [C0402]  14.6 31.01 270 bottom
C564  10u/6.3V_4  [C0402]  15.7 27.26 90 top
C565  10u/6.3V_4  [C0402]  26.08 39.52 90 bottom
C566  1u/10V_6  [C0603]  15.77 36.62 180 bottom
C567  1u/10V_6  [C0603]  15.29 34.59 270 bottom
C568  0.1u/6.3V_2  [C0201]  16.18 27.34 0 bottom
C569  10u/6.3V_4  [C0402]  16.22 28.46 180 bottom
C572  10u/6.3V_4  [C0402]  18.03 37.14 180 bottom
C573  10u/6.3V_4  [C0402]  20.15 26.03 90 bottom
C574  10u/6.3V_4  [C0402]  19.35 39.9 0 bottom
C575  0.1u/6.3V_2  [C0201]  19.45 38.63 180 bottom
C576  10u/6.3V_4  [C0402]  22.65 39.39 180 bottom
C577  0.1u/6.3V_2  [C0201]  22.65 38.25 0 bottom
C578  10u/6.3V_4  [C0402]  28.62 31.65 180 bottom
C580  0.1u/6.3V_2  [C0201]  26.4 35.04 0 bottom
C581  10u/6.3V_4  [C0402]  26.46 35.89 180 bottom
C583  33p/25V_2  [C0201]  28.49 34.44 270 bottom
C584  0.1u/6.3V_2  [C0201]  27.99 29.49 180 bottom
C585  10u/6.3V_4  [C0402]  28.62 30.63 180 bottom
C586  *1000p/25V_2  [C0201]  22.27 23.01 0 top
C587  *22p/25V_2  [C0201]  25.32 32.41 90 bottom
C588  *0.1u/6.3V_2  [C0201]  15.41 15.39 315 top
C589  4.7u/6.3V_6  [C0603]  15.6 23.75 90 bottom
C590  100p/50V_2  [C0201]  6.53 14.75 180 top
C591  100p/50V_2  [C0201]  21.36 26.36 180 top
C592  100p/50V_2  [C0201]  15.77 19.53 180 bottom
C593  100p/50V_2  [C0201]  9.81 28.48 270 bottom
C594  4.7u/6.3V_6  [C0603]  17.07 24.46 90 bottom
C595  *1u/25V_4  [C0402]  30.27 32.66 90 bottom
C596  *0.1u/6.3V_2  [C0201]  11.73 34.16 0 bottom
C597  *10u/6.3V_4  [C0402]  8.32 31.84 270 bottom
C598  *10u/6.3V_4  [C0402]  12.36 28.88 270 bottom
C599  *0.1u/6.3V_2  [C0201]  15.49 25.93 270 bottom
C601  P2_P2SPIN@1000p/25V_2  [C0201]  84.12 197.51 0 bottom
C602  P2_P2SPIN@1000p/25V_2  [C0201]  81.2 197.58 180 bottom
C603  P2_P2SPIN@1000p/25V_2  [C0201]  88.56 197.51 0 bottom
C604  P2_P2SPIN@1000p/25V_2  [C0201]  85.77 197.51 180 bottom
C613  *10p/25V_2  [C0201]  15.41 130.07 270 top
C614  *10p/25V_2  [C0201]  15.41 131.21 90 top
C616  220p/25V_2  [C0201]  15.03 133.25 90 bottom
C631  0.1u/6.3V_2  [C0201]  26.33 168.93 0 top
C632  0.1u/6.3V_2  [C0201]  26.21 170.05 0 top
C633  0.1u/6.3V_2  [C0201]  21.89 173.12 180 top
C634  0.1u/6.3V_2  [C0201]  18.33 173.25 90 top
C635  0.1u/6.3V_2  [C0201]  15.67 164.23 90 bottom
C636  0.1u/6.3V_2  [C0201]  17.09 164.23 90 bottom
C638  10p/25V_2  [C0201]  29.38 168.17 0 top
C639  10p/25V_2  [C0201]  29.38 170.96 0 top
C641  0.1u/6.3V_2  [C0201]  19.86 173 180 top
C642  0.1u/6.3V_2  [C0201]  15.03 168.04 180 top
C645  8111K@0.01u/50V_4  [C0402]  39.54 179.47 90 top
C646  10p/3KV_1808  [C1808]  29.31 191.11 180 bottom
C669  *HDD@47u/6.3V_8  [C0805]  228.39 106.83 180 top
C670  HDD@10u/6.3V_4  [C0402]  228.77 103.15 90 top
C680  *HDD@0.1u/6.3V_2  [C0201]  227.63 103.15 270 top
C689  *HDD@0.1u/6.3V_2  [C0201]  226.61 103.15 270 top
C695  0.1u/6.3V_2  [C0201]  133.35 98.69 0 top
C696  10p/25V_2  [C0201]  133.42 96.83 0 top
C697  10p/25V_2  [C0201]  129.95 97.07 180 top
C698  *10p/25V_2  [C0201]  129 98.75 180 top
C699  *10p/25V_2  [C0201]  127.57 98.76 0 top
C706  220p/25V_2  [C0201]  177.82 98.83 270 top
C707  220p/25V_2  [C0201]  176.09 98.73 270 top
C708  220p/25V_2  [C0201]  174.62 98.73 270 top
C709  220p/25V_2  [C0201]  178.56 98.83 270 top
C711  220p/25V_2  [C0201]  179.29 98.83 270 top
C713  220p/25V_2  [C0201]  180.03 98.83 270 top
C714  220p/25V_2  [C0201]  180.77 98.83 270 top
C715  220p/25V_2  [C0201]  181.66 98.83 270 top
C716  220p/25V_2  [C0201]  172.74 98.57 270 top
C717  220p/25V_2  [C0201]  173.45 98.57 270 top
C718  220p/25V_2  [C0201]  175.36 98.73 270 top
C719  220p/25V_2  [C0201]  172.03 98.83 270 top
C720  220p/25V_2  [C0201]  189.66 98.83 270 top
C721  220p/25V_2  [C0201]  191.43 98.83 270 top
C722  220p/25V_2  [C0201]  188.77 98.83 270 top
C723  220p/25V_2  [C0201]  187.88 98.83 270 top
C724  220p/25V_2  [C0201]  192.32 98.83 270 top
C725  220p/25V_2  [C0201]  186.1 98.83 270 top
C726  220p/25V_2  [C0201]  190.55 98.83 270 top
C727  220p/25V_2  [C0201]  186.99 98.83 270 top
C728  220p/25V_2  [C0201]  182.54 98.7 270 top
C729  220p/25V_2  [C0201]  183.43 98.7 270 top
C730  220p/25V_2  [C0201]  184.32 98.73 270 top
C731  220p/25V_2  [C0201]  185.21 98.73 270 top
C732  220p/25V_2  [C0201]  170.61 98.88 270 top
C733  220p/25V_2  [C0201]  171.32 98.88 270 top
C734  *2.2u/10V_4  [C0402]  213.53 122.96 180 bottom
C736  4.7u/6.3V_4  [C0402]  219.5 121.21 180 bottom
C737  0.01u/50V_4  [C0402]  220.42 122.75 0 bottom
C740  10u/6.3V_4  [C0402]  93.26 100.1 90 top
C741  0.1u/6.3V_2  [C0201]  83.87 96.95 180 top
C742  0.1u/6.3V_2  [C0201]  92.38 100.48 270 top
C743  10u/6.3V_4  [C0402]  92.76 95.04 0 top
C744  0.1u/6.3V_2  [C0201]  83.87 96.21 180 top
C745  0.1u/6.3V_2  [C0201]  93.24 97.33 270 top
C749  *2.2u/10V_4  [C0402]  114.85 106.07 180 top
C750  *0.01u/50V_4  [C0402]  112.95 105.58 0 bottom
C752  4.7u/6.3V_4  [C0402]  116 104.29 0 bottom
C753  0.01u/50V_4  [C0402]  116 103.27 0 bottom
C770  *10u/6.3V_4  [C0402]  221.66 109.5 0 top
C771  10u/6.3V_4  [C0402]  221.66 110.77 0 top
C772  0.1u/6.3V_2  [C0201]  221.66 108.35 180 top
C785  *SSD@0.1u/6.3V_2  [C0201]  32.95 69.07 90 bottom
C786  SSD@0.1u/6.3V_2  [C0201]  33.71 69.07 90 bottom
C788  SSD@0.22u/6.3V_2  [C0201]  32.81 83.59 270 bottom
C789  SSD@0.22u/6.3V_2  [C0201]  32.05 83.59 270 bottom
C790  SSD@0.22u/6.3V_2  [C0201]  29.13 83.59 270 bottom
C791  SSD@0.22u/6.3V_2  [C0201]  28.37 83.59 270 bottom
C792  SSD@0.22u/6.3V_2  [C0201]  25.97 83.72 270 bottom
C793  SSD@0.22u/6.3V_2  [C0201]  25.19 83.72 270 bottom
C794  SSD@0.22u/6.3V_2  [C0201]  22.65 83.72 270 bottom
C795  SSD@0.22u/6.3V_2  [C0201]  21.89 83.72 270 bottom
C800  *0.1u/6.3V_2  [C0201]  194.74 122.53 90 bottom
C801  0.01u/10V_2  [C0201]  195.5 122.53 90 bottom
C802  10u/6.3V_4  [C0402]  193.34 103.4 90 bottom
C804  0.1u/6.3V_2  [C0201]  193.67 123.82 90 bottom
C805  10u/6.3V_4  [C0402]  196.81 122.44 0 bottom
C841  *0.1u/6.3V_2  [C0201]  147.62 210.59 180 top
C842  0.1u/6.3V_2  [C0201]  151.05 213.89 90 top
C844  100p/50V_2  [C0201]  26.33 29.36 180 bottom
C845  10u/6.3V_4  [C0402]  16.66 38.4 270 bottom
C846  0.1u/6.3V_2  [C0201]  25.19 29.36 0 bottom
C856  *CRT@10p/25V_2  [C0201]  18.84 152.93 270 top
C857  *CRT@10p/25V_2  [C0201]  19.1 154.45 90 top
C858  *CRT@10p/25V_2  [C0201]  19.73 156.23 90 top
C859  CRT@10p/25V_2  [C0201]  16.43 156.23 90 top
C860  CRT@10p/25V_2  [C0201]  16.43 154.96 270 top
C861  CRT@10p/25V_2  [C0201]  16.05 153.18 90 top
C890  CRT@0.1u/6.3V_2  [C0201]  11.48 159.41 180 bottom
C900  *CRT@0.1u/6.3V_2  [C0201]  13.89 148.87 0 top
C1044  *0.1u/25V_2  [C0201]  15.92 147.22 270 bottom
C1189  0.1u/6.3V_2  [C0201]  149.35 106.52 180 top
C1190  0.1u/6.3V_2  [C0201]  149.35 105.76 180 top
C1208  180p/25V_2  [C0201]  169.59 104.04 180 top
C1210  180p/25V_2  [C0201]  170.2 103.17 90 top
C1211  1u/10V_2  [C0201]  80.31 105.81 270 top
C1214  1u/10V_2  [C0201]  77.85 100.61 0 top
C1217  1u/10V_2  [C0201]  80.56 103.98 90 top
C1643  5.6p/25V_2  [C0201]  33.07 50.95 90 bottom
C1644  5.6p/25V_2  [C0201]  33.07 51.97 270 bottom
C1645  5.6p/25V_2  [C0201]  32.81 36.22 90 bottom
C1646  5.6p/25V_2  [C0201]  32.81 37.23 270 bottom
C1647  5.6p/25V_2  [C0201]  32.81 40.28 90 bottom
C1648  5.6p/25V_2  [C0201]  33.07 47.77 90 bottom
C1649  1u/10V_2  [C0201]  24.56 65.68 270 bottom
C1650  4.7u/6.3V_4  [C0402]  29.51 66.95 180 bottom
C1651  1u/10V_2  [C0201]  33.57 64.28 0 bottom
C1652  0.1u/6.3V_2  [C0201]  29.76 65.94 270 bottom
C1653  0.1u/6.3V_2  [C0201]  30.78 65.94 270 bottom
C2374  *180p/25V_2  [C0201]  149.78 100.28 90 top
C2609  0.1u/6.3V_2  [C0201]  195.88 103.4 270 bottom
C2616  *SSD@0.1u/6.3V_2  [C0201]  16.3 70.41 90 bottom
C6554  EV@0.22u/6.3V_2  [C0201]  129.71 210.21 270 top
C6555  EV@0.22u/6.3V_2  [C0201]  129.97 208.3 270 top
C6556  EV@0.22u/6.3V_2  [C0201]  128.95 210.21 270 top
C6557  EV@0.22u/6.3V_2  [C0201]  130.73 208.3 270 top
C6560  *220p/25V_2  [C0201]  16.17 129.82 270 bottom
C6562  *10p/25V_2  [C0201]  147.95 105.41 0 top
C6563  180p/25V_2  [C0201]  150.41 110.92 90 top
C6564  10u/6.3V_4  [C0402]  172 95.4 0 top
C6565  0.1u/6.3V_2  [C0201]  169.64 108.15 270 top
C6566  0.1u/6.3V_2  [C0201]  171.5 101.22 90 top
C6568  180p/25V_2  [C0201]  169.08 96.42 0 top
C6569  0.1u/6.3V_2  [C0201]  170.38 108.15 270 top
C6570  0.1u/6.3V_2  [C0201]  170.61 95.65 0 top
C6571  1u/10V_2  [C0201]  147.09 104.01 90 top
C6572  180p/25V_2  [C0201]  161.54 115.47 90 top
C6573  0.1u/6.3V_2  [C0201]  151.18 112.62 270 top
C6574  0.1u/6.3V_2  [C0201]  154.48 113.05 90 top
C6575  0.1u/6.3V_2  [C0201]  159.96 112.65 0 top
C6577  0.1u/6.3V_2  [C0201]  148.97 98.19 270 top
C6578  0.1u/6.3V_2  [C0201]  149.7 98.19 270 top
C6580  180p/25V_2  [C0201]  168.7 112.8 90 top
C6586  HDD@0.01u/10V_2  [C0201]  231.06 119.4 90 top
C6587  HDD@0.01u/10V_2  [C0201]  230.3 119.4 90 top
C6588  HDD@0.01u/10V_2  [C0201]  229.53 119.4 90 top
C6589  HDD@0.01u/10V_2  [C0201]  228.77 119.4 90 top
C6594  HDD@0.01u/10V_2  [C0201]  231 111.72 90 top
C6595  HDD@0.01u/10V_2  [C0201]  230.27 111.72 90 top
C6596  HDD@0.01u/10V_2  [C0201]  229.51 111.72 90 top
C6597  HDD@0.01u/10V_2  [C0201]  228.77 111.72 90 top
C6598  HDD@0.1u/6.3V_2  [C0201]  232.48 119.02 90 top
C6599  HDD@0.1u/6.3V_2  [C0201]  233.22 119.02 90 top
C6600  HDD@0.1u/6.3V_2  [C0201]  226.36 112.8 270 top
C6601  HDD@0.1u/6.3V_2  [C0201]  231.77 119.02 90 top
C6602  HDD@0.1u/6.3V_2  [C0201]  227.12 112.8 270 top
C6607  HDD@10u/6.3V_4  [C0402]  225.34 112.67 90 top
C6610  0.1u/6.3V_2  [C0201]  149.65 103.53 270 top
C6615  0.1u/6.3V_2  [C0201]  209.29 97.34 180 top
C6616  180p/25V_2  [C0201]  66.97 186.46 90 top
C20000  0.1u/6.3V_2  [C0201]  25.83 167.79 90 top
C20001  *180p/25V_2  [C0201]  66.47 188.74 270 top
C20002  *180p/25V_2  [C0201]  67.99 186.46 90 top
C20003  *CRT@2p/25V_2  [C0201]  13.76 160.17 180 top
C20004  *CRT@10p/25V_2  [C0201]  14.14 157.25 270 top
C20005  *CRT@220p/25V_2  [C0201]  11.48 158.65 180 bottom
C20006  *CRT@10p/25V_2  [C0201]  13.76 161.19 180 top
C20008  *CRT@2p/25V_2  [C0201]  13.76 159.03 0 top
C20009  CRT@0.22u/6.3V_2  [C0201]  11.48 157.88 0 bottom
C20010  *CRT@2.2u/10V_4  [C0402]  29.89 146.45 270 top
C20011  CRT@0.1u/6.3V_2  [C0201]  29.76 148.1 90 top
C20012  CRT@0.1u/6.3V_2  [C0201]  26.59 153.95 180 top
C20013  CRT@0.1u/6.3V_2  [C0201]  25.95 156.61 0 top
C20014  CRT@0.1u/6.3V_2  [C0201]  35.73 151.41 180 top
C20015  CRT@0.1u/6.3V_2  [C0201]  35.73 150.64 180 top
C20016  CRT@0.1u/6.3V_2  [C0201]  35.73 153.18 180 top
C20017  CRT@0.1u/6.3V_2  [C0201]  35.73 153.95 180 top
C20018  CRT@0.1u/6.3V_2  [C0201]  35.73 154.84 180 top
C20019  CRT@0.1u/6.3V_2  [C0201]  35.73 155.6 180 top
C20020  CRT@0.1u/6.3V_2  [C0201]  35.73 152.3 180 top
C20021  CRT@0.1u/6.3V_2  [C0201]  26.46 150.01 270 top
C20022  CRT@2.2u/10V_4  [C0402]  27.48 149.89 90 top
C20023  *CRT@0.1u/6.3V_2  [C0201]  35.1 148.49 90 top
C20039  SM@47p/25V_2  [C0201]  224.2 93.24 0 top
C20040  SM@1u/25V_4  [C0402]  211 95.71 0 top
C20041  SM@0.1u/6.3V_2  [C0201]  224.2 98.07 0 top
C20042  SM@1u/25V_4  [C0402]  224.2 99.08 180 top
C20043  SM@0.1u/6.3V_2  [C0201]  210.99 97.94 180 top
C20044  SM@0.1u/6.3V_2  [C0201]  224.2 101.11 0 top
C20045  SM@1u/25V_4  [C0402]  224.2 100.1 0 top
C20046  SM@0.1u/6.3V_2  [C0201]  210.99 99.97 180 top
C20047  SM@1u/25V_4  [C0402]  210.99 98.96 180 top
C20048  SM@0.1u/6.3V_2  [C0201]  222.3 102.51 90 top
C20049  SM@1u/25V_4  [C0402]  221.41 102.51 90 top
C20050  SM@1u/25V_4  [C0402]  215.98 101.88 180 top
C20051  SM@82p/25V_2  [C0201]  215.95 102.89 180 top
C20053  *SM@47p/25V_2  [C0201]  224.33 95.12 0 top
C20099  0.1u/6.3V_2  [C0201]  63.26 106.61 0 top
C20100  2.2u/10V_4  [C0402]  64.28 107.12 270 top
C20101  0.1u/6.3V_2  [C0201]  57.07 128.55 180 top
C20102  2.2u/10V_4  [C0402]  57.07 127.66 180 top
C20103  *0.1u/6.3V_2  [C0201]  55.04 144.55 90 top
C20104  1u/10V_2  [C0201]  56.36 159.16 90 top
C20105  1u/10V_2  [C0201]  56.31 104.54 270 top
C20106  1u/10V_2  [C0201]  64.39 104.4 90 top
C20107  1u/10V_2  [C0201]  58.94 139.89 0 top
C20108  1u/10V_2  [C0201]  57.83 104.54 270 top
C20109  *1u/10V_2  [C0201]  65.15 104.4 90 top
C20110  1u/10V_2  [C0201]  66.77 121.2 90 top
C20111  *1u/10V_2  [C0201]  55.54 104.54 270 top
C20112  10u/6.3V_4  [C0402]  65.32 106.07 270 top
C20113  1u/10V_2  [C0201]  67.04 111.06 180 top
C20114  *1u/10V_2  [C0201]  57.07 104.54 270 top
C20115  *10u/6.3V_4  [C0402]  63.16 105.05 0 top
C20116  *1u/10V_2  [C0201]  55.46 168.62 0 top
C20117  10u/6.3V_4  [C0402]  55.11 106.94 0 top
C20118  *1u/10V_2  [C0201]  55.45 153.12 0 top
C20119  *10u/6.3V_4  [C0402]  57.58 106.32 270 top
C20120  *1u/10V_2  [C0201]  56.26 114.76 270 top
C20121  *1u/10V_2  [C0201]  67.23 161.82 270 top
C20122  10u/6.3V_4  [C0402]  63.25 141.52 0 top
C20123  10u/6.3V_4  [C0402]  67.74 128.8 180 top
C20124  10u/6.3V_4  [C0402]  52.88 133.37 270 top
C20125  10u/6.3V_4  [C0402]  67.74 135.66 180 top
C20126  *10u/6.3V_4  [C0402]  58.76 132.04 180 top
C20127  *10u/6.3V_4  [C0402]  67.38 144.77 270 top
C20128  *10u/6.3V_4  [C0402]  67.74 132.1 180 top
C20129  *10u/6.3V_4  [C0402]  57.77 135.33 180 top
C20130  0.022u/25V_4  [C0402]  57.4 121.43 90 top
C20131  0.1u/6.3V_2  [C0201]  30.78 172.74 0 top
C20132  1000p/25V_2  [C0201]  27.22 173.63 0 top
C20133  SPIN@0.1u/6.3V_2  [C0201]  142.01 216.84 180 top
C20134  SPIN@10u/6.3V_4  [C0402]  139.49 215.16 270 top
C20135  SPIN_EXT@0.1u/6.3V_2  [C0201]  135.68 213.26 180 top
C20138  SPIN_EXT@0.1u/6.3V_2  [C0201]  156.89 211.35 270 bottom
C20140  SPIN_EXT@0.1u/6.3V_2  [C0201]  153.46 210.46 0 top
C20141  SPIN_EXT@0.1u/6.3V_2  [C0201]  155.52 210.46 0 top
C20142  SPIN_EXT@1u/10V_2  [C0201]  156 214.4 90 bottom
C20143  HDD@0.01u/10V_2  [C0201]  225.6 103.15 270 top
C96242  *HDD@47u/6.3V_8  [C0805]  228.39 108.86 180 top
C96247  IR@10u/6.3V_4  [C0402]  37.16 191.64 90 bottom
C96248  IR@1u/10V_2  [C0201]  38.12 191.69 270 bottom
C96249  IR@4.7u/6.3V_4  [C0402]  36.19 191.69 270 bottom
C96265  *100p/50V_2  [C0201]  7.4 28.57 0 bottom
C96266  *100p/50V_2  [C0201]  15.77 20.55 0 bottom
C96267  *100p/50V_2  [C0201]  8.82 28.48 90 bottom
C96268  *100p/50V_2  [C0201]  19.32 26.21 180 top
C96269  0.1u/6.3V_2  [C0201]  94.01 187.76 270 bottom
C96270  2200p/25V_2  [C0201]  94.03 186.71 270 bottom
C96271  0.1u/6.3V_2  [C0201]  201.59 126.01 90 bottom
C96272  2200p/25V_2  [C0201]  202.05 124.33 270 bottom
C96300  0.1u/6.3V_2  [C0201]  25.83 164.36 270 top
C96301  0.1u/6.3V_2  [C0201]  23.54 173.12 0 top
C96302  10u/6.3V_4  [C0402]  19.81 173.95 180 top
C96303  10u/6.3V_4  [C0402]  23.63 172.25 0 top
C96304  0.1u/6.3V_2  [C0201]  15.79 160.3 270 top
C96305  1u/10V_2  [C0201]  16.68 160.3 270 top
C96306  0.1u/6.3V_2  [C0201]  18.59 160.93 270 top
C96307  0.1u/6.3V_2  [C0201]  17.83 160.93 270 top
C96308  I219@1u/10V_2  [C0201]  26.97 164.87 270 top
C96309  I219@22u/6.3V_6  [C0603]  20.82 175.16 0 top
C96310  I219@0.1u/6.3V_2  [C0201]  21.13 176.43 180 top
C96311  I219@10u/6.3V_4  [C0402]  15.41 162.71 180 bottom
C96312  I219@10u/6.3V_4  [C0402]  13.25 164.23 90 bottom
C96313  I219@1u/50V_6  [C0603]  37.51 179.47 90 top
C96319  0.1u/6.3V_2  [C0201]  32.81 41.55 270 bottom
C96320  4.7u/6.3V_4  [C0402]  31.67 41.55 90 bottom
C96343  SPIN@0.1u/6.3V_2  [C0201]  137.08 211.73 180 top
C96344  0.01u/10V_2  [C0201]  194.74 122.53 90 top
C96346  *180p/25V_2  [C0201]  161.84 113.05 180 bottom
C96545  0.1u/6.3V_2  [C0201]  30.91 123.09 0 top
C96546  0.1u/6.3V_2  [C0201]  30.91 123.85 0 top
C96547  0.1u/6.3V_2  [C0201]  30.91 124.74 0 top
C96548  0.1u/6.3V_2  [C0201]  30.91 125.5 0 top
C96549  0.1u/6.3V_2  [C0201]  30.91 126.26 0 top
C96550  0.1u/6.3V_2  [C0201]  30.91 127.02 0 top
C96551  0.1u/6.3V_2  [C0201]  30.91 128.8 0 top
C96552  0.1u/6.3V_2  [C0201]  30.91 129.56 0 top
C96553  *3.3p/25V_2  [C0201]  16.43 128.29 270 top
C96554  1u/10V_2  [C0201]  29.64 121.05 180 top
C96555  0.01u/50V_4  [C0402]  18.84 127.91 180 top
C96556  0.1u/6.3V_2  [C0201]  18.46 124.86 90 top
C96557  0.1u/6.3V_2  [C0201]  19.22 124.86 90 top
C96558  0.01u/50V_4  [C0402]  25.7 119.78 0 top
C96559  0.1u/6.3V_2  [C0201]  25.06 120.93 180 top
C96560  1u/10V_2  [C0201]  30.91 133.25 90 top
C96561  0.1u/6.3V_2  [C0201]  29.64 132.36 0 top
C96562  0.01u/50V_4  [C0402]  21.13 120.8 180 top
C96563  0.1u/6.3V_2  [C0201]  21.13 121.69 0 top
C96564  0.1u/6.3V_2  [C0201]  29.64 130.58 180 top
C96565  10u/6.3V_4  [C0402]  29.64 131.47 180 top
C96566  0.01u/50V_4  [C0402]  25.19 131.39 180 top
C96567  0.1u/6.3V_2  [C0201]  23.29 130.2 270 top
C96568  0.1u/6.3V_2  [C0201]  25.57 130.53 0 top
C96569  0.1u/6.3V_2  [C0201]  30.78 127.91 90 top
C96570  0.1u/6.3V_2  [C0201]  31.54 127.91 90 top
C96571  0.01u/50V_4  [C0402]  32.43 127.73 270 top
C96572  10u/6.3V_4  [C0402]  33.45 127.73 90 top
C96574  *0.1u/6.3V_2  [C0201]  92.25 117.37 180 top
C96575  10u/6.3V_4  [C0402]  112.1 145.69 270 top
C96576  *10u/6.3V_4  [C0402]  110.77 155.09 0 top
C96577  22u/6.3V_6  [C0603]  111.23 153.76 0 top
C96578  *10u/6.3V_4  [C0402]  127.55 163.47 0 bottom
C96579  22u/6.3V_6  [C0603]  108.46 145.93 270 top
C96580  10u/6.3V_4  [C0402]  109.33 141.98 270 top
C96581  *10u/6.3V_4  [C0402]  115.36 168.81 180 top
C96582  10u/6.3V_4  [C0402]  113.16 147.51 90 top
C96583  22u/6.3V_6  [C0603]  109.9 145.93 270 top
C96584  *10u/6.3V_4  [C0402]  128.32 161.95 90 bottom
C96585  10u/6.3V_4  [C0402]  113.16 145.69 270 top
C96586  *10u/6.3V_4  [C0402]  113.69 170.84 0 top
C96587  22u/6.3V_6  [C0603]  111.74 149.38 0 top
C96588  10u/6.3V_4  [C0402]  111.66 143.94 90 top
C96589  1u/10V_2  [C0201]  132.51 153.9 90 top
C96590  10u/6.3V_4  [C0402]  111.1 147.51 90 top
C96591  *10u/6.3V_4  [C0402]  114.22 149.4 180 top
C96592  *1u/10V_2  [C0201]  131.49 154.2 270 top
C96593  22u/6.3V_6  [C0603]  111.74 150.81 0 top
C96594  22u/6.3V_6  [C0603]  111.23 152.35 0 top
C96595  10u/6.3V_4  [C0402]  115.67 140.45 90 top
C96596  22u/6.3V_6  [C0603]  129.84 163.73 180 bottom
C96597  *10u/6.3V_4  [C0402]  114.22 150.61 180 top
C96598  10u/6.3V_4  [C0402]  116.84 142.2 270 top
C96599  22u/6.3V_6  [C0603]  127.68 165.5 270 bottom
C96600  *10u/6.3V_4  [C0402]  113.69 171.85 0 top
C96601  1u/10V_2  [C0201]  127.11 140.81 180 bottom
C96602  *1u/10V_2  [C0201]  127.41 142.02 0 bottom
C96603  10u/6.3V_4  [C0402]  109.33 143.72 90 top
C96604  22u/6.3V_6  [C0603]  110.15 170.84 0 bottom
C96605  *10u/6.3V_4  [C0402]  115.41 169.82 180 top
C96606  10u/6.3V_4  [C0402]  108.26 143.72 90 top
C96607  22u/6.3V_6  [C0603]  115.31 168.98 180 bottom
C96608  *10u/6.3V_4  [C0402]  115.41 171.85 180 top
C96609  10u/6.3V_4  [C0402]  108.26 141.95 270 top
C96610  10u/6.3V_4  [C0402]  115.46 171.17 180 bottom
C96611  10u/6.3V_4  [C0402]  115.36 146.71 270 top
C96612  *10u/6.3V_4  [C0402]  114.22 153.74 180 top
C96613  *1u/10V_2  [C0201]  113.55 140.49 270 top
C96614  *10u/6.3V_4  [C0402]  112.11 147.51 90 top
C96615  *10u/6.3V_4  [C0402]  116.54 146.12 90 top
C96616  *1u/10V_2  [C0201]  114.51 140.49 270 top
C96617  *10u/6.3V_4  [C0402]  112.84 143.94 90 top
C96618  *10u/6.3V_4  [C0402]  117.56 146.11 90 top
C96619  *1u/10V_2  [C0201]  111.3 142.06 90 top
C96620  *10u/6.3V_4  [C0402]  111.1 145.69 270 top
C96621  10u/6.3V_4  [C0402]  110.49 168.68 0 bottom
C96622  *1u/10V_2  [C0201]  113.95 143.94 270 top
C96623  *10u/6.3V_4  [C0402]  110.45 143.75 90 top
C96624  *10u/6.3V_4  [C0402]  127.3 161.95 90 bottom
C96625  1u/10V_2  [C0201]  134.11 152.52 90 top
C96626  *1u/10V_2  [C0201]  114.91 143.94 270 top
C96627  *10u/6.3V_4  [C0402]  114.7 148.18 180 top
C96628  10u/6.3V_4  [C0402]  113.74 171.17 0 bottom
C96629  *1u/10V_2  [C0201]  115.74 167.79 0 top
C96630  *10u/6.3V_4  [C0402]  115.66 142.2 270 top
C96631  *10u/6.3V_4  [C0402]  129.33 161.95 90 bottom
C96632  *1u/10V_2  [C0201]  114.19 152.73 0 top
C96633  *10u/6.3V_4  [C0402]  112.42 142.17 270 top
C96634  *10u/6.3V_4  [C0402]  114.22 151.8 180 top
C96635  *1u/10V_2  [C0201]  111.81 172.11 0 top
C96636  *10u/6.3V_4  [C0402]  116.85 140.45 90 top
C96637  *10u/6.3V_4  [C0402]  115.41 170.84 180 top
C96638  *1u/10V_2  [C0201]  111.81 171.35 0 top
C96639  10u/6.3V_4  [C0402]  113.74 170.2 0 bottom
C96640  *1u/10V_2  [C0201]  115.93 143.97 270 top
C96641  10u/6.3V_4  [C0402]  115.46 170.2 180 bottom
C96642  *1u/10V_2  [C0201]  116.89 143.97 270 top
C96643  1u/10V_2  [C0201]  133.4 153.9 90 top
C96644  10u/6.3V_4  [C0402]  110.49 169.64 0 bottom
C96645  *1u/10V_2  [C0201]  113.46 169.95 180 top
C96646  *10u/6.3V_4  [C0402]  112.75 155.09 0 top
C96647  *10u/6.3V_4  [C0402]  110.17 157.32 0 top
C96648  *1u/10V_2  [C0201]  90.5 131.29 270 top
C96649  47u/6.3V_6  [C0603]  109.06 148.11 180 top
C96650  1u/10V_2  [C0201]  92.55 156.87 90 top
C96651  *1u/10V_2  [C0201]  91.74 154.33 270 top
C96652  47u/6.3V_6  [C0603]  109.06 149.55 180 top
C96653  1u/10V_2  [C0201]  90.09 138.07 90 top
C96654  *1u/10V_2  [C0201]  92.5 154.33 270 top
C96655  1u/10V_2  [C0201]  88.69 131.29 270 top
C96656  *1u/10V_2  [C0201]  92.5 133.63 270 top
C96657  1u/10V_2  [C0201]  92.5 137.69 90 top
C96658  *1u/10V_2  [C0201]  108.63 133.75 0 top
C96659  1u/10V_2  [C0201]  91.13 146.91 270 top
C96660  10u/6.3V_4  [C0402]  108.66 150.77 180 top
C96661  *1u/10V_2  [C0201]  90.65 157.76 270 top
C96662  1u/10V_2  [C0201]  92.37 146.91 270 top
C96663  10u/6.3V_4  [C0402]  108.66 151.91 180 top
C96664  *1u/10V_2  [C0201]  90.6 148.1 270 top
C96665  1u/10V_2  [C0201]  91.74 142.47 270 top
C96666  10u/6.3V_4  [C0402]  108.66 153.06 180 top
C96667  *1u/10V_2  [C0201]  88.31 138.07 90 top
C96668  1u/10V_2  [C0201]  90.09 128.67 90 top
C96669  10u/6.3V_4  [C0402]  108.66 154.12 180 top
C96670  *1u/10V_2  [C0201]  87.47 129.69 270 top
C96671  *1u/10V_2  [C0201]  91.79 140.48 270 top
C96672  10u/6.3V_4  [C0402]  108.66 155.09 180 top
C96673  *1u/10V_2  [C0201]  91.13 129.69 270 top
C96674  *1u/10V_2  [C0201]  92.5 142.47 270 top
C96675  10u/6.3V_4  [C0402]  108.51 157.24 270 top
C96676  *1u/10V_2  [C0201]  92.5 159.28 270 top
C96677  *1u/10V_2  [C0201]  92.5 151.74 90 top
C96678  10u/6.3V_4  [C0402]  108.66 136.17 180 top
C96679  *1u/10V_2  [C0201]  92.12 162.07 270 top
C96680  *1u/10V_2  [C0201]  91.87 160.93 270 top
C96681  10u/6.3V_4  [C0402]  108.66 137.56 180 top
C96682  *1u/10V_2  [C0201]  90.34 144.68 270 top
C96683  *1u/10V_2  [C0201]  89.83 148.1 270 top
C96684  10u/6.3V_4  [C0402]  108.66 134.64 180 top
C96685  *1u/10V_2  [C0201]  91.23 151.74 90 top
C96686  *1u/10V_2  [C0201]  91.36 138.07 90 top
C96687  10u/6.3V_4  [C0402]  91.61 133.5 90 top
C96688  *1u/10V_2  [C0201]  90.6 150.14 0 top
C96689  *1u/10V_2  [C0201]  92.55 140.48 270 top
C96690  *1u/10V_2  [C0201]  91.79 156.87 90 top
C96691  *1u/10V_2  [C0201]  89.33 128.67 90 top
C96692  *1u/10V_2  [C0201]  90.85 154.33 270 top
C96693  *1u/10V_2  [C0201]  88.69 133.12 270 top
C96694  *1u/10V_2  [C0201]  90.47 133.12 270 top
C96695  *1u/10V_2  [C0201]  89.45 140.87 270 top
C96696  *1u/10V_2  [C0201]  92.25 144.68 270 top
C96700  *10p/25V_2  [C0201]  96.46 122.2 270 bottom
C96701  0.22u/6.3V_2  [C0201]  130.22 160.8 90 top
C96702  0.22u/6.3V_2  [C0201]  130.86 157.76 0 top
C96703  0.22u/6.3V_2  [C0201]  131.24 160.8 90 top
C96704  0.22u/6.3V_2  [C0201]  130.86 156.99 0 top
C96705  0.22u/6.3V_2  [C0201]  131.49 159.41 0 top
C96706  0.22u/6.3V_2  [C0201]  129.08 156.74 0 top
C96707  0.22u/6.3V_2  [C0201]  131.49 158.65 0 top
C96708  0.22u/6.3V_2  [C0201]  129.08 155.98 0 top
C96709  18p/25V_2  [C0201]  102.53 116.58 0 bottom
C96710  18p/25V_2  [C0201]  103.42 115.85 0 bottom
C96711  10p/25V_2  [R0201]  128.82 123.85 270 bottom
C96713  12p/25V_2  [R0201]  128.82 122.7 90 bottom
C96716  0.1u/6.3V_2  [C0201]  106.73 112.04 0 top
C96717  *0.01u/50V_4  [C0402]  82.85 120.04 0 top
C96718  *10p/25V_2  [C0201]  127.07 145.11 270 bottom
C96719  0.1u/6.3V_2  [C0201]  89.56 105.31 270 top
C96720  22u/6.3V_6  [C0603]  138.6 147.09 90 top
C96721  47u/6.3V_6  [C0603]  140.13 147.09 90 top
C96722  22u/6.3V_6  [C0603]  136.44 152.04 270 top
C96723  10u/6.3V_4  [C0402]  131.87 133.88 90 top
C96724  *1u/10V_2  [C0201]  108.94 132.76 270 top
C96725  47u/6.3V_6  [C0603]  138.35 152.04 270 top
C96726  22u/6.3V_6  [C0603]  140.13 139.34 270 top
C96727  10u/6.3V_4  [C0402]  110.49 134.16 0 top
C96728  10u/6.3V_4  [C0402]  132.89 133.88 90 top
C96729  22u/6.3V_6  [C0603]  140.13 132.99 270 top
C96730  47u/6.3V_6  [C0603]  138.6 132.99 270 top
C96731  10u/6.3V_4  [C0402]  133.9 133.88 90 top
C96732  10u/6.3V_4  [C0402]  116.38 138.45 90 top
C96733  *1u/10V_2  [C0201]  110.03 132.36 180 top
C96734  22u/6.3V_6  [C0603]  140.13 135.66 90 top
C96735  10u/6.3V_4  [C0402]  132.89 131.21 90 top
C96736  10u/6.3V_4  [C0402]  113.71 136.27 180 top
C96737  *47u/6.3V_6  [C0603]  138.6 135.66 90 top
C96738  10u/6.3V_4  [C0402]  136.7 133.5 270 top
C96739  22u/6.3V_6  [C0603]  111.11 136.33 0 top
C96740  10u/6.3V_4  [C0402]  109.39 139.85 270 top
C96741  10u/6.3V_4  [C0402]  136.7 139.21 270 top
C96742  10u/6.3V_4  [C0402]  108.28 139.85 270 top
C96743  22u/6.3V_6  [C0603]  111.11 137.75 0 top
C96744  10u/6.3V_4  [C0402]  134.92 135.79 90 top
C96745  10u/6.3V_4  [C0402]  111.17 135.12 0 top
C96746  22u/6.3V_6  [C0603]  113.73 138.11 90 top
C96747  10u/6.3V_4  [C0402]  134.92 133.88 90 top
C96748  10u/6.3V_4  [C0402]  116.5 149.83 0 top
C96749  22u/6.3V_6  [C0603]  115.17 138.11 90 top
C96750  10u/6.3V_4  [C0402]  134.92 131.21 90 top
C96751  10u/6.3V_4  [C0402]  116.5 148.74 0 top
C96752  22u/6.3V_6  [C0603]  138.6 139.34 270 top
C96753  10u/6.3V_4  [C0402]  136.7 135.79 90 top
C96754  10u/6.3V_4  [C0402]  116.89 147.72 0 top
C96755  22u/6.3V_6  [C0603]  112.11 139.77 270 top
C96756  10u/6.3V_4  [C0402]  131.87 131.21 90 top
C96757  10u/6.3V_4  [C0402]  116.5 151.05 0 top
C96758  *1u/10V_2  [C0201]  113.71 114.7 180 top
C96759  22u/6.3V_6  [C0603]  110.69 139.77 270 top
C96760  10u/6.3V_4  [C0402]  110.49 133.19 0 top
C96761  *0.1u/6.3V_2  [C0201]  113.71 115.47 180 top
C96762  10u/6.3V_4  [C0402]  136.7 131.47 90 top
C96763  10u/6.3V_4  [C0402]  130.86 133.88 90 top
